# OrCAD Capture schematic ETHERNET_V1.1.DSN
size A; title: Ethernet; rev: 1.1; company: nuvoTon Technology Corp.; note: Ethernet
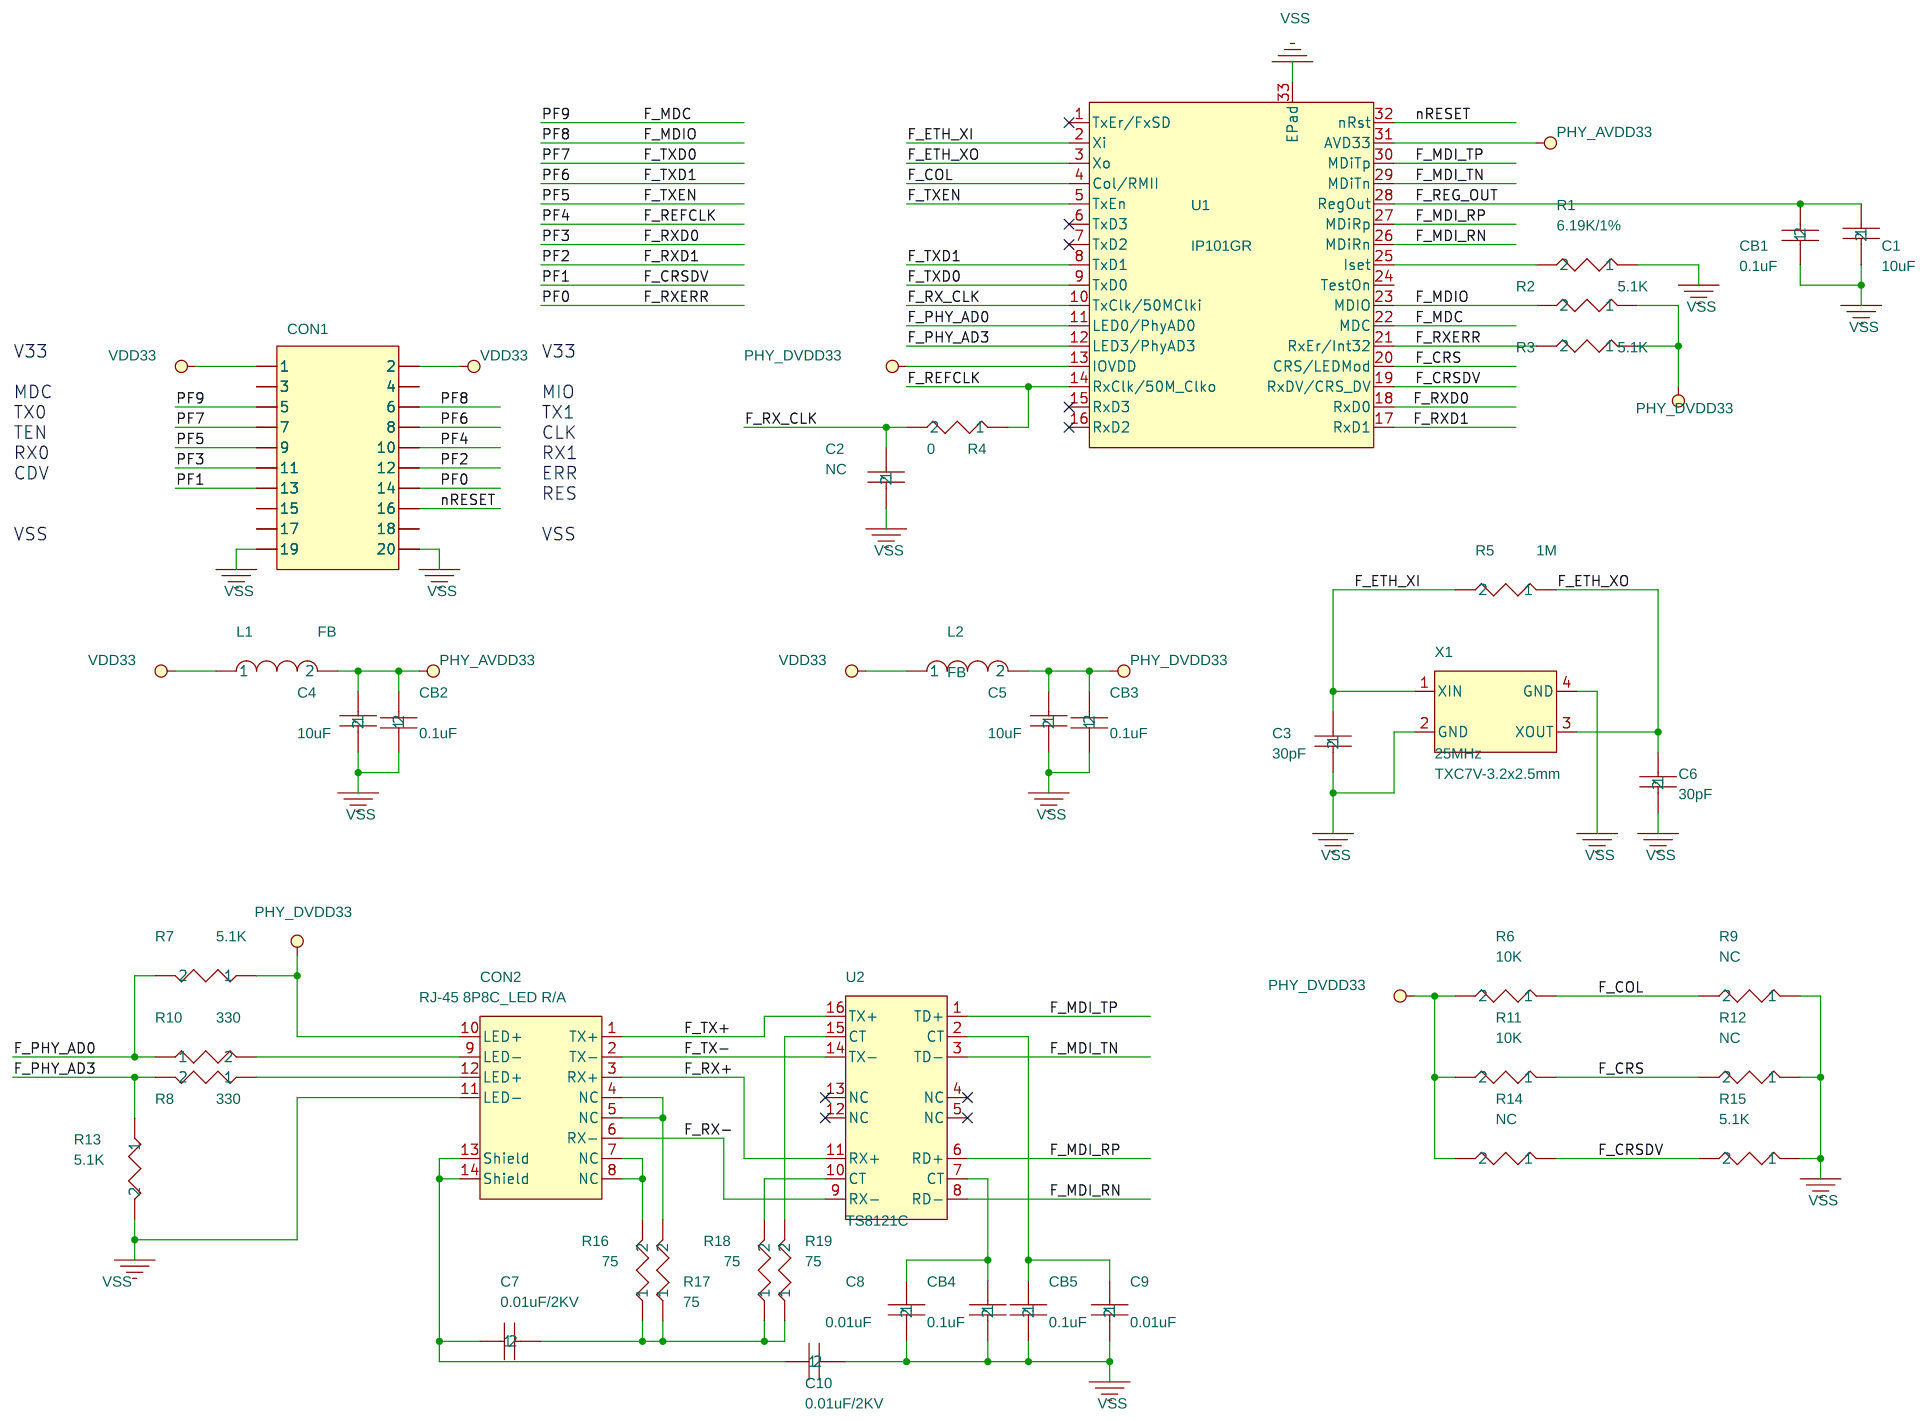
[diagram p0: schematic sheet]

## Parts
C1  10uF  [C0603]
C2  NC  [C0603]
C3  30pF  [C0603]
C4  10uF  [C0603]
C5  10uF  [C0603]
C6  30pF  [C0603]
C7  0.01uF/2KV  [CK05]
C8  0.01uF  [C0603]
C9  0.01uF  [C0603]
C10  0.01uF/2KV  [CK05]
CB1  0.1uF  [C0603]
CB2  0.1uF  [C0603]
CB3  0.1uF  [C0603]
CB4  0.1uF  [C0603]
CB5  0.1uF  [C0603]
CON1  RMII_PF  [FEMALE_2x10_2.54mm]
CON2  RJ-45 8P8C_LED R/A  [RJ45\8P\JA\LED]
L1  FB  [L0603]
L2  FB  [L0603]
R1  6.19K/1%  [R0603]
R2  5.1K  [R0603]
R3  5.1K  [R0603]
R4  0  [R0603]
R5  1M  [R0603]
R6  10K  [R0603]
R7  5.1K  [R0603]
R8  330  [R0603]
R9  NC  [R0603]
R10  330  [R0603]
R11  10K  [R0603]
R12  NC  [R0603]
R13  5.1K  [R0603]
R14  NC  [R0603]
R15  5.1K  [R0603]
R16  75  [R0603]
R17  75  [R0603]
R18  75  [R0603]
R19  75  [R0603]
U1  IP101GR  [QFN32_0.4x4]
U2  TS8121C  [ST6200T]
X1  25MHz  [TXC7V-3.2x2.5mm]

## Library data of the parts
C1 = CAP_NP_14
C2 = CAP_NP_12
C3 = CAP_NP
C4 = CAP_NP_10
C5 = CAP_NP_13
C6 = CAP_NP_6
C7 = CAP_NP_2
C8 = CAP_NP_1
C9 = CAP_NP_4
C10 = CAP_NP_9
CB1 = CAP_NP_7
CB2 = CAP_NP_8
CB3 = CAP_NP_3
CB4 = CAP_NP_5
CB5 = CAP_NP_11
CON1 = CON20A
CON2 = RJ45_SHLD_0
L1 = INDUCTOR_1
L2 = INDUCTOR
R1 = R_9
R2 = R_5
R3 = R_3
R4 = R_7
R5 = R
R6 = R_1
R7 = R_2
R8 = R_12
R9 = R_6
R10 = R_4
R11 = R_10
R12 = R_18
R13 = R_11
R14 = R_8
R15 = R_14
R16 = R_15
R17 = R_16
R18 = R_17
R19 = R_13
U1 = IP101GA_1
U2 = PE-68515_1
X1 = Crystal_SMD_2: Vendor: Aurum

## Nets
VDD33: CON1.1 CON1.2 L1.1 L2.1
VSS: C1.2 C2.2 C3.2 C4.2 C5.2 C6.2 C8.2 C9.2 C10.2 CB1.1 CB2.1 CB3.1 CB4.2 CB5.2 CON1.19 CON1.20 CON2.11(LED-) R1.1 R9.1 R12.1 R13.2 R15.1 U1.33(EPad) X1.2(GND) X1.4(GND)
F_COL: R6.1 R9.2 U1.4(Col/RMII)
F_CRS: R11.1 R12.2 U1.20(CRS/LEDMod)
F_CRSDV: CON1.13 R14.1 R15.2 U1.19(RxDV/CRS_DV)
F_ETH_XI: C3.1 R5.2 U1.2(Xi) X1.1(XIN)
F_ETH_XO: C6.1 R5.1 U1.3(Xo) X1.3(XOUT)
F_MDC: CON1.5 U1.22(MDC)
F_MDI_RN: U1.26(MDiRn) U2.8(RD-)
F_MDI_RP: U1.27(MDiRp) U2.6(RD+)
F_MDI_TN: U1.29(MDiTn) U2.3(TD-)
F_MDI_TP: U1.30(MDiTp) U2.1(TD+)
F_MDIO: CON1.6 R2.2 U1.23(MDIO)
F_PHY_AD0: R7.2 R10.1 U1.11(LED0/PhyAD0)
F_PHY_AD3: R8.2 R13.1 U1.12(LED3/PhyAD3)
F_REFCLK: CON1.10 R4.1 U1.14(RxClk/50M_Clko)
F_REG_OUT: C1.1 CB1.2 U1.28(RegOut)
F_RX+: CON2.3(RX+) U2.11(RX+)
F_RX-: CON2.6(RX-) U2.9(RX-)
F_RX_CLK: C2.1 R4.2 U1.10(TxClk/50MClki)
F_RXD0: CON1.11 U1.18(RxD0)
F_RXD1: CON1.12 U1.17(RxD1)
F_RXERR: CON1.14 R3.2 U1.21(RxEr/Int32)
F_TX+: CON2.1(TX+) U2.16(TX+)
F_TX-: CON2.2(TX-) U2.14(TX-)
F_TXD0: CON1.7 U1.9(TxD0)
F_TXD1: CON1.8 U1.8(TxD1)
F_TXEN: CON1.9 U1.5(TxEn)
nRESET: CON1.16 U1.32(nRst)
PHY_AVDD33: C4.1 CB2.2 L1.2 U1.31(AVD33)
PHY_DVDD33: C5.1 CB3.2 CON2.10(LED+) L2.2 R2.1 R3.1 R6.2 R7.1 R11.2 R14.2 U1.13(IOVDD)
N16822422: C9.1 CB5.1 U2.2(CT)
N16822428: C7.1 C10.1 CON2.13(Shield) CON2.14(Shield)
N16822432: R18.2 U2.10(CT)
N16822441: R19.2 U2.15(CT)
N16822454: CON2.7(NC) CON2.8(NC) R16.2
N16822462: CON2.4(NC) CON2.5(NC) R17.2
N16822677: C8.1 CB4.1 U2.7(CT)
N16822679: CON2.9(LED-) R10.2
N16822715: C7.2 R16.1 R17.1 R18.1 R19.1
N16822844: CON2.12(LED+) R8.1
N16823008: R1.2 U1.25(Iset)

Not connected (* = marked no-connect by the designer): CON1 3 4 15 17 18; U1 1(TxEr/FxSD)* 6(TxD3)* 7(TxD2)* 15(RxD3)* 16(RxD2)* 24(TestOn); U2 4(NC)* 5(NC)* 12(NC)* 13(NC)*

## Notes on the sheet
- V33
- V33
- MDC
- MIO
- TX0
- TX1
- TEN
- CLK
- RX0
- RX1
- CDV
- ERR
- RES
- VSS
- VSS
